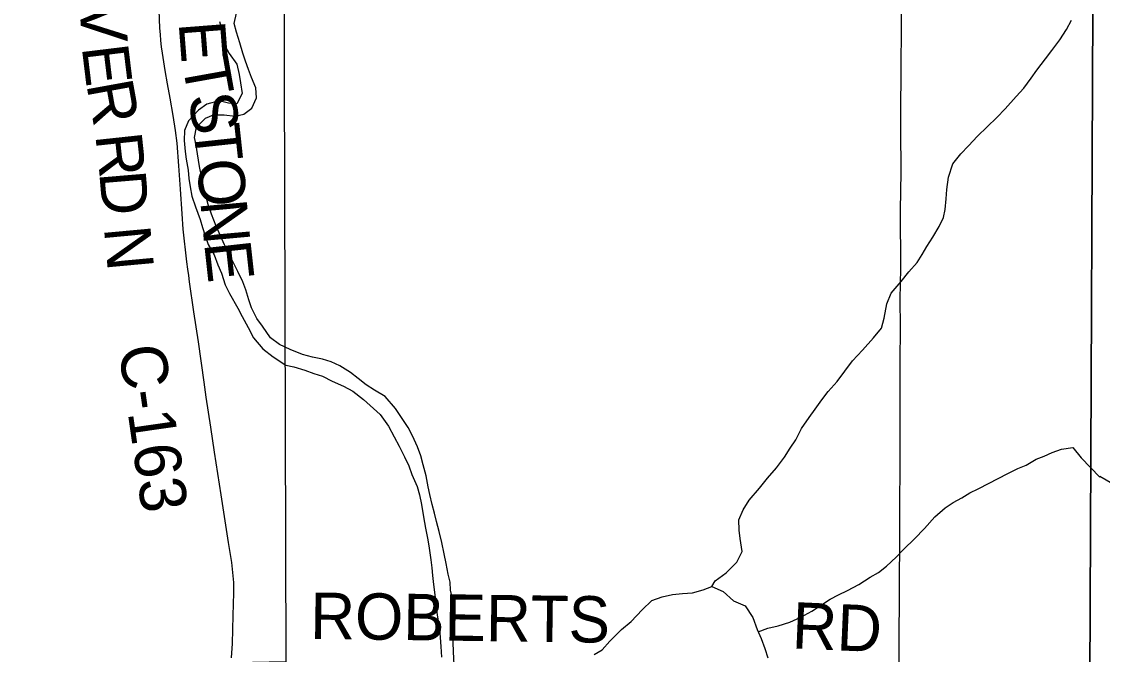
# Model space of a CAD drawing. Extents: x 0 to 45.9, y 0 to 22.
# Drawn here: x 4.156 to 5.48, y 16.732 to 17.508 of the extents above; entities that cross this region are included whole.
import ezdxf

# ---------------------------------------------------------------- set-up
doc = ezdxf.new("R2010")
doc.units = 0
for name, color, linetype in [('Default', 7, 'Continuous'), ('GM_X_County_Road', 7, 'Continuous'), ('GM_X_County_Road_Text', 7, 'Continuous'), ('GM_X_Major_River', 7, 'Continuous'), ('GM_X_Minor_River', 7, 'Continuous'), ('GM_X_Section', 7, 'Continuous'), ('GM_X_State_Route', 7, 'Continuous'), ('GM_X_Township_Road_Text', 7, 'Continuous'), ('SH_Text', 7, 'Continuous')]:
    doc.layers.add(name, color=color, linetype=linetype)

msp = doc.modelspace()

# ---------------------------------------------------------------- linework, layer by layer
at = {"layer": 'Default'}
msp.add_lwpolyline([(2.1, 19.7114), (2.1, 14.1), (5.4538, 14.1), (5.4606, 15.6588), (5.4651, 16.7018), (5.4694, 17.7061), (5.4802, 18.3214), (5.4737, 18.7216), (5.4752, 19.0482), (5.4759, 19.2109), (5.4773, 19.7108), (5.0826, 19.712), (3.7367, 19.7072), (2.15, 19.7113)], close=True, dxfattribs=at)
msp.add_lwpolyline([(5.4773, 19.7108), (5.4759, 19.2109), (5.4752, 19.0482), (5.4737, 18.7216), (5.4802, 18.3214), (5.4694, 17.7061), (5.4651, 16.7018), (5.4606, 15.6588), (5.4538, 14.1)], dxfattribs=at)
at = {"layer": 'GM_X_County_Road'}
msp.add_lwpolyline([(4.4133, 16.7278), (4.4147, 16.7455), (4.4155, 16.7796), (4.4161, 16.8076), (4.416, 16.82), (4.4151, 16.8325), (4.4137, 16.8448), (4.4118, 16.8569), (4.4098, 16.8694), (4.4006, 16.9277), (4.3924, 16.9798), (4.3879, 17.0105), (4.3825, 17.0474), (4.38, 17.0658), (4.373, 17.115), (4.3673, 17.1519), (4.362, 17.1887), (4.361, 17.1965), (4.3599, 17.2041), (4.3587, 17.2133), (4.3543, 17.2534), (4.3527, 17.2719), (4.3508, 17.3024), (4.349, 17.3308), (4.3466, 17.3586), (4.3448, 17.3741), (4.3419, 17.3925), (4.338, 17.4139), (4.3348, 17.4315), (4.3321, 17.4475), (4.3287, 17.4689), (4.3277, 17.4768), (4.3268, 17.4843), (4.3263, 17.4917), (4.3257, 17.4997), (4.3248, 17.5214)], dxfattribs=at)
at = {"layer": 'GM_X_Major_River'}
for points in [[(4.3986, 17.5078), (4.4022, 17.4949), (4.4036, 17.4812), (4.4106, 17.4686), (4.4199, 17.4555), (4.4228, 17.4426), (4.4245, 17.4327), (4.4266, 17.4194), (4.42, 17.407), (4.4098, 17.4075), (4.3984, 17.4103), (4.3832, 17.4063), (4.3729, 17.3989), (4.3605, 17.3858), (4.3558, 17.3741), (4.3553, 17.3619), (4.3566, 17.3483), (4.358, 17.3388), (4.3601, 17.3255), (4.3611, 17.3152), (4.3625, 17.3049), (4.3646, 17.2935), (4.3694, 17.2806), (4.3748, 17.2649), (4.3777, 17.2554), (4.381, 17.2451), (4.3847, 17.2345), (4.3921, 17.2218), (4.3965, 17.2096), (4.4009, 17.1993), (4.4056, 17.1849), (4.4108, 17.1745), (4.4212, 17.1562), (4.4263, 17.1463), (4.4337, 17.1325), (4.4404, 17.1199), (4.4516, 17.1065), (4.4644, 17.0968), (4.4798, 17.0867), (4.4896, 17.0843), (4.5032, 17.0804), (4.5142, 17.0764), (4.5248, 17.0729), (4.5368, 17.067), (4.5504, 17.0607), (4.5621, 17.0545), (4.5752, 17.0445), (4.5955, 17.026), (4.6055, 17.0118), (4.6125, 16.9988), (4.6188, 16.9874), (4.6255, 16.9744), (4.6307, 16.9633), (4.6343, 16.9526), (4.6409, 16.9377), (4.6435, 16.9278), (4.6463, 16.9157), (4.6484, 16.9008), (4.6512, 16.8868), (4.6537, 16.8723), (4.6555, 16.8621), (4.6575, 16.848), (4.6586, 16.8381), (4.6596, 16.8286), (4.6609, 16.8176), (4.6623, 16.8051), (4.6637, 16.7948), (4.6654, 16.78), (4.6682, 16.764), (4.6688, 16.7526), (4.6698, 16.7416), (4.6707, 16.7287)], [(4.6862, 16.719), (4.6852, 16.7357), (4.685, 16.7467), (4.6848, 16.7562), (4.6853, 16.7661), (4.6866, 16.7767), (4.6867, 16.7896), (4.6846, 16.7991), (4.6817, 16.8109), (4.6811, 16.8207), (4.6789, 16.8306), (4.6765, 16.8436), (4.674, 16.8554), (4.6711, 16.8691), (4.6679, 16.8828), (4.6646, 16.8949), (4.6621, 16.9052), (4.6592, 16.9159), (4.6564, 16.9281), (4.6542, 16.9376), (4.6517, 16.9509), (4.6481, 16.9646), (4.6452, 16.9756), (4.6412, 16.9863), (4.635, 17), (4.6298, 17.01), (4.6209, 17.0238), (4.6142, 17.0333), (4.6015, 17.0483), (4.5887, 17.0561), (4.5785, 17.0626), (4.5687, 17.0704), (4.559, 17.0777), (4.5462, 17.0858), (4.5356, 17.0905), (4.5247, 17.0937), (4.5126, 17.0965), (4.5005, 17.0997), (4.4854, 17.1056), (4.4722, 17.1119), (4.4613, 17.12), (4.4512, 17.1342), (4.4445, 17.1437), (4.4379, 17.1567), (4.4346, 17.1666), (4.431, 17.1788), (4.4273, 17.1887), (4.421, 17.2013), (4.4144, 17.2143), (4.4048, 17.2342), (4.4, 17.2449), (4.3945, 17.2567), (4.389, 17.2716), (4.3846, 17.2834), (4.3817, 17.2941), (4.3792, 17.3055), (4.3771, 17.3161), (4.3742, 17.3298), (4.3718, 17.3454), (4.37, 17.3561), (4.3682, 17.3656), (4.3703, 17.3781), (4.3815, 17.3893), (4.3914, 17.3933), (4.4043, 17.3932), (4.4179, 17.3918), (4.4286, 17.3943), (4.4382, 17.4014), (4.444, 17.4142), (4.4431, 17.4264), (4.4379, 17.439), (4.4343, 17.4489), (4.4306, 17.4592), (4.4273, 17.4687), (4.4237, 17.4817), (4.4193, 17.4946), (4.4168, 17.5053), (4.4193, 17.5178)]]:
    msp.add_lwpolyline(points, dxfattribs=at)
at = {"layer": 'GM_X_Minor_River'}
for points in [[(5.002, 16.8153), (5.0059, 16.8224), (5.0193, 16.8321), (5.0324, 16.8452), (5.039, 16.858), (5.0366, 16.874), (5.0352, 16.8843), (5.035, 16.8968), (5.0401, 16.9092), (5.0475, 16.9209), (5.0602, 16.9359), (5.0702, 16.9479), (5.081, 16.9607), (5.0907, 16.9738), (5.098, 16.9847), (5.1046, 16.9952), (5.1116, 17.0088), (5.1209, 17.0223), (5.1283, 17.0325), (5.1368, 17.0441), (5.1445, 17.0543), (5.1553, 17.0666), (5.1646, 17.079), (5.1742, 17.0918), (5.1866, 17.1049), (5.2, 17.1199), (5.2097, 17.1319), (5.2129, 17.144), (5.2162, 17.1618), (5.2217, 17.1746), (5.2336, 17.1889), (5.2433, 17.2009), (5.2533, 17.2125), (5.2595, 17.2223), (5.2653, 17.2321), (5.2727, 17.2434), (5.2804, 17.2565), (5.2855, 17.2675), (5.2876, 17.2773), (5.2889, 17.2902), (5.2898, 17.3019), (5.2919, 17.3171), (5.297, 17.3333), (5.3067, 17.3457), (5.3163, 17.3554), (5.3275, 17.3671), (5.3509, 17.3899), (5.3613, 17.4007), (5.3748, 17.4157), (5.3841, 17.4262), (5.393, 17.4383), (5.3999, 17.448), (5.4107, 17.4619), (5.4185, 17.4721), (5.4281, 17.4852), (5.4363, 17.498), (5.4425, 17.5093)], [(5.0586, 16.7598), (5.0704, 16.7643), (5.0833, 16.7671), (5.0974, 16.7715), (5.1108, 16.7778), (5.1245, 16.7852), (5.1349, 16.7922), (5.1467, 16.7997), (5.1571, 16.8052), (5.1681, 16.8104), (5.1819, 16.8178), (5.1957, 16.8267), (5.206, 16.8326), (5.216, 16.8401), (5.2275, 16.8513), (5.2371, 16.861), (5.2502, 16.8738), (5.2625, 16.8865), (5.2752, 16.9007), (5.2879, 16.9116), (5.2975, 16.9183), (5.3082, 16.9238), (5.3181, 16.9301), (5.3281, 16.9349), (5.3418, 16.942), (5.3518, 16.9471), (5.3651, 16.9542), (5.3766, 16.9601), (5.3869, 16.9641), (5.3991, 16.9712), (5.4091, 16.9752), (5.4186, 16.9796), (5.4304, 16.9836), (5.4441, 16.9857), (5.4542, 16.9731), (5.4772, 16.9494)], [(5.4772, 16.9504), (5.5035, 16.9353)], [(4.8575, 16.7319), (4.8674, 16.7378), (4.877, 16.7483), (4.8913, 16.7625), (4.9028, 16.7726), (4.9163, 16.7868), (4.9285, 16.7981), (4.9411, 16.8028), (4.9537, 16.8053), (4.9659, 16.8067), (4.978, 16.8076), (4.9913, 16.8112), (5.002, 16.8153), (5.0156, 16.809), (5.0283, 16.7978), (5.0427, 16.7916), (5.052, 16.7774), (5.0575, 16.7626), (5.0622, 16.7515), (5.0666, 16.7393), (5.0703, 16.7279)]]:
    msp.add_lwpolyline(points, dxfattribs=at)
at = {"layer": 'GM_X_Section'}
msp.add_lwpolyline([(3.4888, 17.7149), (4.477, 17.7336), (4.4801, 16.7228), (3.479, 16.7029)], close=True, dxfattribs=at)
at = {"layer": 'GM_X_State_Route'}
msp.add_lwpolyline([(5.2313, 16.7102), (5.2315, 16.7416), (5.2316, 16.8131), (5.2321, 16.8784), (5.2322, 16.9219), (5.2324, 16.9561), (5.2324, 17.0089), (5.2326, 17.0898), (5.2328, 17.1333), (5.2327, 17.1675), (5.2332, 17.2048), (5.2331, 17.2763), (5.2336, 17.3229), (5.2335, 17.3758), (5.2335, 17.4006), (5.2338, 17.4442), (5.2342, 17.5063), (5.2341, 17.5405)], dxfattribs=at)
at = {"layer": 'SH_Text'}
for points in [[(5.4538, 14.1), (5.4606, 15.6588), (5.4651, 16.7018), (5.4694, 17.7061), (5.4802, 18.3214), (5.4737, 18.7216), (5.4752, 19.0482), (5.4759, 19.2109), (5.4773, 19.7108)], [(5.4773, 19.7108), (5.4759, 19.2109), (5.4752, 19.0482), (5.4737, 18.7216), (5.4802, 18.3214), (5.4694, 17.7061), (5.4651, 16.7018), (5.4606, 15.6588), (5.4538, 14.1)]]:
    msp.add_lwpolyline(points, dxfattribs=at)

# ---------------------------------------------------------------- texts
at = {"layer": 'GM_X_County_Road_Text'}
for s, height, rotation, p in [('V', 0.0568, 272.2709, (4.2274, 17.5315)), ('E', 0.0568, 274.4434, (4.3485, 17.5063)), ('E', 0.0568, 276.9534, (4.2298, 17.4765)), ('T', 0.0568, 280.1904, (4.3526, 17.4578)), ('R', 0.0568, 280.2728, (4.2354, 17.4309)), ('S', 0.0568, 279.3014, (4.3601, 17.4162)), ('T', 0.0568, 276.1358, (4.3662, 17.3792)), ('R', 0.0568, 276.1355, (4.2464, 17.3687)), ('O', 0.0568, 275.0846, (4.3707, 17.3372)), ('D', 0.0568, 274.7993, (4.2513, 17.3227)), ('N', 0.0568, 275.127, (4.3751, 17.2874)), ('N', 0.0568, 275.2805, (4.257, 17.2549)), ('E', 0.0568, 276.3735, (4.3797, 17.2362)), ('C-163', 0.05682, 278.2102, (4.2747, 17.108))]:
    msp.add_text(s, height=height, rotation=rotation, dxfattribs=at).set_placement(p)
at = {"layer": 'GM_X_Township_Road_Text'}
for s, rotation, p in [('ROBERTS', 359.2384, (4.5095, 16.7512)), ('RD', 357.5333, (5.0993, 16.7395))]:
    msp.add_text(s, height=0.05682, rotation=rotation, dxfattribs=at).set_placement(p)

doc.saveas('drawing.dxf')
